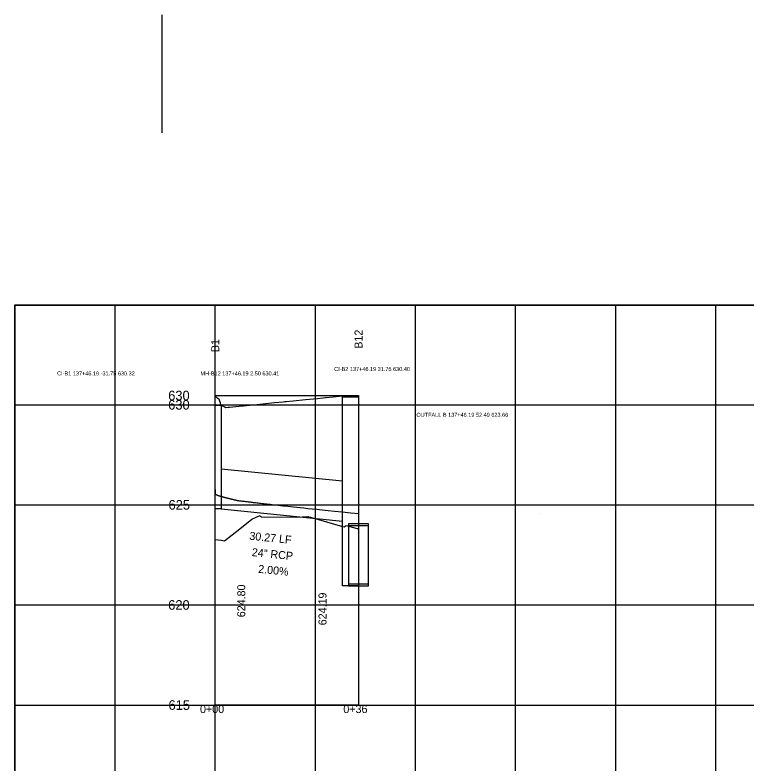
# Model space of a CAD drawing. Extents: x 2253035 to 2279930, y 13774972 to 13793443.
# Drawn here: x 2276749.4 to 2276931.9, y 13792678.1 to 13792865 of the extents above; entities that cross this region are included whole.
import ezdxf

# ---------------------------------------------------------------- set-up
doc = ezdxf.new("R2010")
doc.units = 0
for name, color, linetype in [('Default', 7, 'Continuous'), ('E_Utility_ATT_HH', 7, 'Continuous'), ('E_Utility_ATT_PR_PVC', 7, 'Continuous'), ('E_Utility_Electric_Overhead Electric Power Line_OE_Elevation', 7, 'Continuous'), ('E_Utility_Electric_Overhead Electric Power Line_OE_point', 7, 'Continuous'), ('E_Utility_Electric_Power Pole_PP_point', 7, 'Continuous'), ('E_Utility_Telephone_Manhole Telephone_MHT_point', 7, 'Continuous'), ('E_Utility_Telephone_Telephone Pedestal_TPED_Description', 7, 'Continuous'), ('E_Utility_Water_Water Meter_WM_Description', 7, 'Continuous'), ('E_Utillity_Water_Water Line_12in', 7, 'Continuous'), ('E_Utillity_Water_Water Line_1in', 7, 'Continuous'), ('E_Utillity_Water_Water Line_4in', 7, 'Continuous'), ('E_Utillity_Water_Water Line_8in', 7, 'Continuous')]:
    doc.layers.add(name, color=color, linetype=linetype)

msp = doc.modelspace()

# ---------------------------------------------------------------- linework, layer by layer
at = {"layer": 'E_Utility_ATT_PR_PVC'}
msp.add_line((2276880.57, 13792740.53), (2276880.57, 13792740.53), dxfattribs=at)
msp.add_lwpolyline([(2276799.4, 13792746.46), (2276799.4, 13792745.35), (2276799.4, 13792745.35), (2276799.41, 13792745.34), (2276799.41, 13792745.34), (2276799.41, 13792745.33), (2276799.41, 13792745.32), (2276799.41, 13792745.32), (2276799.42, 13792745.31), (2276799.42, 13792745.31), (2276799.43, 13792745.3), (2276799.43, 13792745.3), (2276799.44, 13792745.29), (2276799.44, 13792745.28), (2276799.45, 13792745.28), (2276799.46, 13792745.27), (2276799.47, 13792745.26), (2276799.47, 13792745.26), (2276799.48, 13792745.25), (2276799.49, 13792745.24), (2276799.5, 13792745.24), (2276799.51, 13792745.23), (2276799.53, 13792745.22), (2276799.54, 13792745.21), (2276799.55, 13792745.21), (2276799.56, 13792745.2), (2276799.58, 13792745.19), (2276799.59, 13792745.18), (2276799.61, 13792745.18), (2276799.62, 13792745.17), (2276799.64, 13792745.16), (2276799.66, 13792745.15), (2276799.68, 13792745.14), (2276799.7, 13792745.13), (2276799.72, 13792745.12), (2276799.74, 13792745.11), (2276799.76, 13792745.11), (2276799.78, 13792745.1), (2276799.8, 13792745.09), (2276799.83, 13792745.08), (2276799.85, 13792745.07), (2276799.88, 13792745.06), (2276799.91, 13792745.05), (2276799.93, 13792745.04), (2276799.96, 13792745.03), (2276799.99, 13792745.01), (2276800.02, 13792745), (2276800.05, 13792744.99), (2276800.08, 13792744.98), (2276800.12, 13792744.97), (2276800.15, 13792744.96), (2276800.19, 13792744.95), (2276800.22, 13792744.93), (2276800.26, 13792744.92), (2276800.3, 13792744.91), (2276800.34, 13792744.89), (2276800.38, 13792744.88), (2276800.42, 13792744.87), (2276800.46, 13792744.85), (2276800.51, 13792744.84), (2276800.55, 13792744.83), (2276800.6, 13792744.81), (2276800.65, 13792744.8), (2276800.69, 13792744.78), (2276800.74, 13792744.77), (2276800.8, 13792744.75), (2276800.85, 13792744.74), (2276800.9, 13792744.72), (2276800.96, 13792744.71), (2276801.02, 13792744.69), (2276801.08, 13792744.67), (2276801.14, 13792744.66), (2276801.2, 13792744.64), (2276801.26, 13792744.62), (2276801.33, 13792744.6), (2276801.39, 13792744.58), (2276801.46, 13792744.56), (2276801.53, 13792744.55), (2276801.6, 13792744.53), (2276801.68, 13792744.51), (2276801.75, 13792744.49), (2276801.83, 13792744.47), (2276801.91, 13792744.44), (2276801.99, 13792744.42), (2276802.08, 13792744.4), (2276802.16, 13792744.38), (2276802.25, 13792744.36), (2276802.34, 13792744.33), (2276802.43, 13792744.31), (2276802.53, 13792744.29), (2276802.63, 13792744.26), (2276802.73, 13792744.24), (2276802.83, 13792744.21), (2276802.93, 13792744.19), (2276803.04, 13792744.16), (2276803.15, 13792744.13), (2276803.27, 13792744.1), (2276803.38, 13792744.08), (2276803.5, 13792744.05), (2276803.62, 13792744.02), (2276803.75, 13792743.99), (2276803.88, 13792743.96), (2276804.01, 13792743.93), (2276804.15, 13792743.89), (2276804.29, 13792743.86), (2276804.43, 13792743.83), (2276804.58, 13792743.79), (2276804.73, 13792743.76), (2276804.88, 13792743.72), (2276805.04, 13792743.7), (2276805.21, 13792743.68), (2276805.38, 13792743.65), (2276805.55, 13792743.63), (2276805.73, 13792743.61), (2276805.91, 13792743.59), (2276806.1, 13792743.56), (2276806.3, 13792743.54), (2276806.5, 13792743.51), (2276806.7, 13792743.49), (2276806.92, 13792743.46), (2276807.14, 13792743.43), (2276807.36, 13792743.41), (2276807.6, 13792743.38), (2276807.84, 13792743.35), (2276808.09, 13792743.32), (2276808.35, 13792743.29), (2276808.61, 13792743.26), (2276808.89, 13792743.22), (2276809.17, 13792743.19), (2276809.47, 13792743.16), (2276809.77, 13792743.12), (2276810.09, 13792743.08), (2276810.42, 13792743.04), (2276810.76, 13792743.01), (2276811.12, 13792742.97), (2276811.49, 13792742.92), (2276811.87, 13792742.88), (2276812.28, 13792742.83), (2276812.69, 13792742.79), (2276813.13, 13792742.74), (2276813.59, 13792742.69), (2276814.07, 13792742.63), (2276814.57, 13792742.58), (2276815.1, 13792742.52), (2276815.66, 13792742.46), (2276816.25, 13792742.4), (2276816.87, 13792742.33), (2276817.53, 13792742.26), (2276818.23, 13792742.18), (2276818.97, 13792742.1), (2276819.77, 13792742.02), (2276820.62, 13792741.93), (2276821.54, 13792741.83), (2276822.53, 13792741.73), (2276823.62, 13792741.62), (2276824.8, 13792741.49), (2276826.11, 13792741.36), (2276827.56, 13792741.21), (2276829.2, 13792741.04), (2276831.07, 13792740.84), (2276833.24, 13792740.62), (2276835.17, 13792740.42)], dxfattribs=at)
at = {"layer": 'E_Utility_Electric_Overhead Electric Power Line_OE_Elevation'}
for p, q in [((2276799.4, 13792767.6), (2276835.17, 13792767.6)), ((2276799.4, 13792742.6), (2276835.17, 13792742.6)), ((2276799.4, 13792717.6), (2276835.17, 13792717.6))]:
    msp.add_line(p, q, dxfattribs=at)
at = {"layer": 'E_Utility_Electric_Overhead Electric Power Line_OE_point'}
msp.add_lwpolyline([(2276799.4, 13792692.6), (2276799.4, 13792769.91), (2276835.17, 13792769.91), (2276835.17, 13792692.6)], close=True, dxfattribs=at)
at = {"layer": 'E_Utility_Electric_Power Pole_PP_point'}
msp.add_line((2276786.13, 13792835.56), (2276786.13, 13792864.97), dxfattribs=at)
at = {"layer": 'E_Utility_Telephone_Manhole Telephone_MHT_point'}
for p, q in [((2276749.4, 13792792.6), (2277074.4, 13792792.6)), ((2276749.4, 13792492.6), (2276749.4, 13792792.6)), ((2276774.4, 13792492.6), (2276774.4, 13792792.6)), ((2276799.4, 13792492.6), (2276799.4, 13792792.6)), ((2276824.4, 13792492.6), (2276824.4, 13792792.6)), ((2276849.4, 13792492.6), (2276849.4, 13792792.6)), ((2276874.4, 13792492.6), (2276874.4, 13792792.6)), ((2276899.4, 13792492.6), (2276899.4, 13792792.6)), ((2276924.4, 13792492.6), (2276924.4, 13792792.6)), ((2276749.4, 13792767.6), (2277074.4, 13792767.6)), ((2276749.4, 13792742.6), (2277074.4, 13792742.6)), ((2276749.4, 13792717.6), (2277074.4, 13792717.6)), ((2276749.4, 13792692.6), (2277074.4, 13792692.6))]:
    msp.add_line(p, q, dxfattribs=at)
at = {"layer": 'E_Utility_Water_Water Meter_WM_Description'}
msp.add_lwpolyline([(2277133.03, 13792792.44), (2276749.4, 13792792.44), (2276749.4, 13792491.27), (2277133.03, 13792491.27)], close=True, dxfattribs=at)
at = {"layer": 'E_Utillity_Water_Water Line_12in'}
for points in [[(2276831.17, 13792769.59), (2276835.17, 13792769.59), (2276835.17, 13792722.35), (2276831.17, 13792722.35)], [(2276799.4, 13792767.5), (2276800.9, 13792767.5), (2276800.9, 13792741.6), (2276799.4, 13792741.6)]]:
    msp.add_lwpolyline(points, close=True, dxfattribs=at)
at = {"layer": 'E_Utillity_Water_Water Line_1in'}
msp.add_lwpolyline([(2276799.4, 13792733.99), (2276800.9, 13792733.75), (2276800.9, 13792733.75), (2276801.7, 13792733.63), (2276805.5, 13792736.62), (2276808.55, 13792739), (2276809.63, 13792739.55), (2276810.61, 13792739.96), (2276810.68, 13792739.82), (2276810.98, 13792739.6), (2276819.58, 13792739.56), (2276822.51, 13792739.68), (2276822.61, 13792739.67), (2276822.86, 13792739.56), (2276823.14, 13792739.56), (2276823.21, 13792739.56), (2276831.17, 13792737.23), (2276831.17, 13792737.23), (2276831.55, 13792737.12), (2276832.06, 13792737.42), (2276834.85, 13792736.67), (2276834.99, 13792736.67), (2276835.17, 13792736.48)], dxfattribs=at)
at = {"layer": 'E_Utillity_Water_Water Line_4in'}
for p, q in [((2276800.9, 13792751.6), (2276831.17, 13792748.57)), ((2276800.9, 13792741.6), (2276831.17, 13792738.57))]:
    msp.add_line(p, q, dxfattribs=at)
for points in [[(2276832.67, 13792722.86), (2276837.67, 13792722.86), (2276837.67, 13792737.86), (2276832.67, 13792737.86)], [(2276832.67, 13792722.35), (2276837.67, 13792722.35), (2276837.67, 13792737.35), (2276832.67, 13792737.35)]]:
    msp.add_lwpolyline(points, close=True, dxfattribs=at)
at = {"layer": 'E_Utillity_Water_Water Line_8in'}
msp.add_lwpolyline([(2276799.4, 13792769.6), (2276799.55, 13792769.6), (2276800.33, 13792769.07), (2276800.46, 13792768.6), (2276800.59, 13792768.07), (2276800.71, 13792767.6), (2276800.9, 13792767.5), (2276800.9, 13792767.5), (2276801.18, 13792767.37), (2276801.61, 13792767.15), (2276801.87, 13792767.02), (2276801.92, 13792766.99), (2276801.93, 13792766.98), (2276801.97, 13792766.96), (2276802.04, 13792766.93), (2276802.59, 13792766.98), (2276802.61, 13792766.98), (2276802.93, 13792767.01), (2276805.36, 13792767.26), (2276806.4, 13792767.36), (2276806.46, 13792767.37), (2276808.79, 13792767.6), (2276808.94, 13792767.61), (2276809.04, 13792767.62), (2276814.22, 13792768.14), (2276816.36, 13792768.35), (2276816.74, 13792768.39), (2276817.12, 13792768.43), (2276818.83, 13792768.6), (2276821.9, 13792768.9), (2276824.9, 13792769.2), (2276826.32, 13792769.34), (2276826.96, 13792769.41), (2276827.11, 13792769.42), (2276828.88, 13792769.6), (2276831.17, 13792769.83), (2276831.17, 13792769.83), (2276831.92, 13792769.9), (2276835.07, 13792769.6), (2276835.17, 13792769.59)], dxfattribs=at)

# ---------------------------------------------------------------- texts
at = {"layer": 'Default'}
for s, height, p in [('630', 2.4, (2276787.66, 13792768.71)), ('630', 2.4, (2276787.66, 13792766.4)), ('625', 2.4, (2276787.74, 13792741.4)), ('620', 2.4, (2276787.66, 13792716.4)), ('615', 2.4, (2276787.74, 13792691.4)), ('0+00', 2, (2276795.6, 13792690.6)), ('0+36', 2, (2276831.38, 13792690.6))]:
    msp.add_text(s, height=height, dxfattribs=at).set_placement(p)
at = {"layer": 'E_Utility_ATT_HH'}
for s, rotation, p in [('B12', 90, (2276836.17, 13792781.61)), ('B1', 90, (2276800.4, 13792780.73)), ('30.27 LF', 354.2894, (2276807.84, 13792733.91)), ('24" RCP', 354.2894, (2276808.45, 13792729.83)), ('2.00%', 354.2894, (2276810.05, 13792725.65)), ('624.80', 90, (2276806.9, 13792714.53)), ('624.19', 90, (2276827.18, 13792712.52))]:
    msp.add_text(s, height=2, rotation=rotation, dxfattribs=at).set_placement(p)
at = {"layer": 'E_Utility_Telephone_Telephone Pedestal_TPED_Description'}
for s, p in [('CI-B1 137+46.19 -31.75 630.32', (2276759.93, 13792774.93)), ('MH-B12 137+46.19 2.50 630.41', (2276795.71, 13792774.93)), ('CI-B2 137+46.19 31.75 630.40', (2276829.09, 13792776.03)), ('OUTFALL B 137+46.19 52.49 623.66', (2276849.63, 13792764.6))]:
    msp.add_text(s, height=1, rotation=0, dxfattribs=at).set_placement(p)

doc.saveas('drawing.dxf')
